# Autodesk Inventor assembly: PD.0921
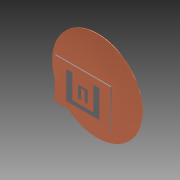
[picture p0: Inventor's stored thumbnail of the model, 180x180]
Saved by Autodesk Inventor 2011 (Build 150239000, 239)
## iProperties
Created: 2014-06
Part Number: PD.0921
Document SubType Name: Assembly
Designer: Evgeny
Author: Evgeny
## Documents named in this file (3)
- D:\Autodesk Invertor 2011\Projects2014\Antenna\Patch900.2100\PD.0921.iam
- D:\Autodesk Invertor 2011\Projects2014\Antenna\Patch900.2100\PD09.21.ipt
- D:\Autodesk Invertor 2011\Projects2014\Antenna\Patch900.2100\PD.Er4.2.ipt
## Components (2 placed, 2 different names)
1. PD09.21:1 — Совмещение:1, Совмещение:2, Совмещение:3
2. PD.Er4.2:1 — Совмещение:1, Совмещение:2, Совмещение:3
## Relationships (3: Mate 3)
- Совмещение:1 [Mate]: PD09.21:1 ↔ PD.Er4.2:1
- Совмещение:2 [Mate]: PD09.21:1 ↔ PD.Er4.2:1
- Совмещение:3 [Mate]: PD09.21:1 ↔ PD.Er4.2:1
